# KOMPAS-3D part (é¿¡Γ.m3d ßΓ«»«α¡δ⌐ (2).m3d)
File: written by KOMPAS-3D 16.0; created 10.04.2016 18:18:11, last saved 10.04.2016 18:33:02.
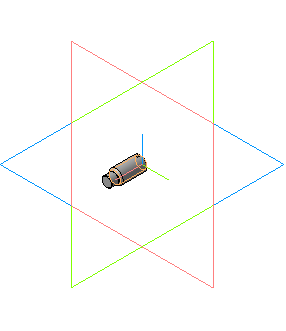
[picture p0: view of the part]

Referenced files in E:\Libs\PartLib\DATA\vault\Methods\Kompas\3D\: PLib_Screw_GOST_1478-84_900.m3d
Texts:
  Винт А.М5-6gx12 ГОСТ 1478-93
  (-) Винт А.М5-6gx12 ГОСТ 1478-93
